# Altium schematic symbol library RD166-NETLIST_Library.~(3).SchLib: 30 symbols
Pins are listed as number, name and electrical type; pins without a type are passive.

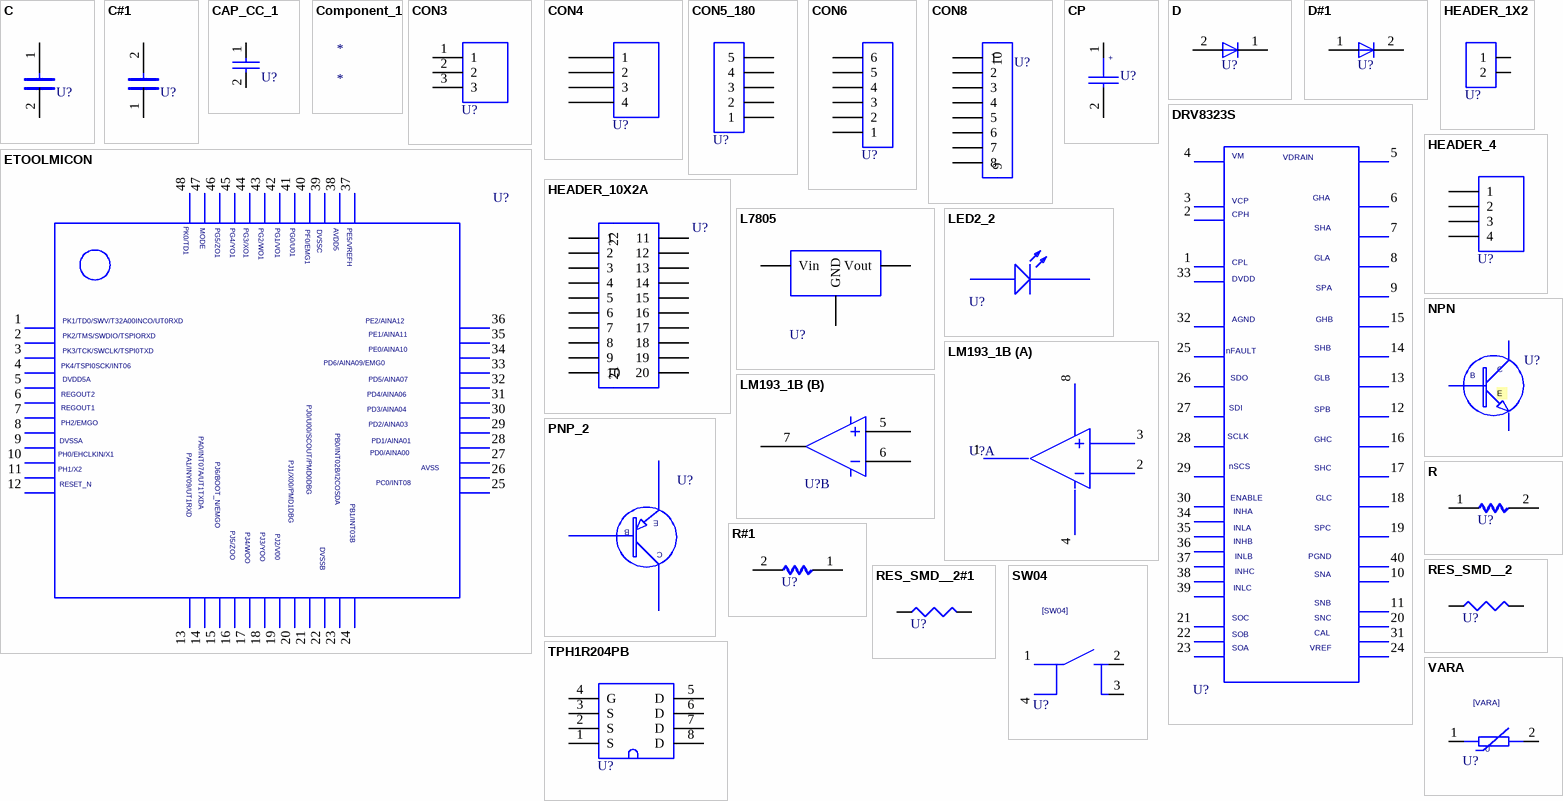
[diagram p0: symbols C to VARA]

## C
designator U?  (value not drawn)
OriginalSymbolOrigin: (2540,7620); Altium-Right: 20; Altium-Bottom: 10
pins: 1 2, 2 1

## C#1
designator U?, comment C  (value not drawn)
OriginalSymbolOrigin: (2540,7620); Altium-Right: 20; Altium-Bottom: 10
pins: 1, 2

## CAP_CC_1
designator U?  (value not drawn)
PARTNAME: CAP-CC_1; OriginalSymbolOrigin: (0,0); SAVECOUNT: 1; UPDATETIME: 14:48:25; UPDATEUSER: d5009410; Altium-Right: 20; Altium-Bottom: 10
pins: 1, 2

## Component_1
designator *

## CON3
designator U?  (value not drawn)
OriginalSymbolOrigin: (0,0); SAVEAREA0: -6361,-10384,8548,546; SAVECOUNT: 2; UPDATETIME: 16:17:55; UPDATEUSER: t5459927; TIME: 14:48:25; Altium-Right: 30; Altium-Bottom: 40
pins: 1, 2, 3

## CON4
designator U?  (value not drawn)
OriginalSymbolOrigin: (0,0); SAVEAREA0: -9538,-12954,9100,710; SAVECOUNT: 2; UPDATETIME: 11:51:19; UPDATEUSER: t5459927; TIME: 14:48:25; Altium-Right: 30; Altium-Bottom: 50
pins: 1, 2, 3, 4

## CON5_180
designator U?  (value not drawn)
OriginalSymbolOrigin: (0,0); SAVEAREA0: -6362,-15544,16003,852; SAVECOUNT: 2; UPDATETIME: 16:18:16; UPDATEUSER: t5459927; TIME: 14:48:25; Altium-Right: 20; Altium-Bottom: 60
pins: 1, 2, 3, 4, 5

## CON6
designator U?  (value not drawn)
OriginalSymbolOrigin: (0,0); SAVEAREA0: -13352,-18135,12740,994; SAVECOUNT: 2; UPDATETIME: 11:51:01; UPDATEUSER: t5459927; TIME: 14:48:25; Altium-Right: 20; Altium-Bottom: 70
pins: 1, 2, 3, 4, 5, 6

## CON8
designator U?  (value not drawn)
OriginalSymbolOrigin: (0,0); SAVEAREA0: -35474,-32561,34839,4331; SAVECOUNT: 3; UPDATETIME: 16:40:52; UPDATEUSER: t5459927; TIME: 14:48:25; Altium-Right: 20; Altium-Bottom: 90
pins: 0 10, 1, 2, 3, 4, 5, 6, 7, 8, 9

## CP
designator U?  (value not drawn)
OriginalSymbolOrigin: (2540,10160); UPDATETIME: 16:13:42; UPDATEUSER: fukuda-y; TIME: 15:02:55; SAVECOUNT: 52; SAVEAREA0: -1450,-153,20294,13055; Altium-Right: 20
pins: 1 2, 2 1

## D
designator U?  (value not drawn)
OriginalSymbolOrigin: (5080,5080); UPDATETIME: 14:20:16; UPDATEUSER: 19870035; TIME: 14:49:55; SAVECOUNT: 3; SAVEAREA0: -225,-91,12804,7836; Altium-Right: 10; Altium-Bottom: 20
pins: 1 C, 2 A

## D#1
designator U?, comment D  (value not drawn)
OriginalSymbolOrigin: (5080,5080); UPDATETIME: 14:20:16; UPDATEUSER: 19870035; TIME: 14:49:55; SAVECOUNT: 3; SAVEAREA0: -225,-91,12804,7836; Altium-Right: 10; Altium-Bottom: 20
pins: 1 A, 2 C

## DRV8323S
designator U?  (value not drawn)
OriginalSymbolOrigin: (-7620,0); SAVEAREA0: -72294,-50031,83425,15115; SAVECOUNT: 5; UPDATETIME: 15:09:32; UPDATEUSER: t5459927; TIME: 14:48:25; Altium-Right: 150; Altium-Bottom: 360
pins: 1, 2, 3, 4, 5, 6, 7, 8, 9, 10, 11, 12, 13, 14, 15, 16, 17, 18, 19, 20, 21, 22, 23, 24, 25, 26, 27, 28, 29, 30, 31, 32, 33, 34, 35, 36, 37, 38, 39, 40

## ETOOLMICON
designator U?  (value not drawn)
OriginalSymbolOrigin: (-10160,7620); SAVEAREA0: -22560,-61894,97211,9095; SAVECOUNT: 11; UPDATETIME: 15:48:18; UPDATEUSER: t5459927; TIME: 14:48:25; Altium-Right: 320; Altium-Bottom: 300
pins: 1, 2, 3, 4, 5, 6, 7, 8, 9, 10, 11, 12, 13, 14, 15, 16, 17, 18, 19, 20, 21, 22, 23, 24, 25, 26, 27, 28, 29, 30, 31, 32, 33, 34, 35, 36, 37, 38, 39, 40, 41, 42, 43, 44, 45, 46, 47, 48

## HEADER_1X2
designator U?  (value not drawn)
PARTNAME: Header 1X2; OriginalSymbolOrigin: (0,0); SAVEAREA0: -1901,-7788,9280,409; SAVECOUNT: 2; UPDATETIME: 11:52:06; UPDATEUSER: t5459927; TIME: 14:48:25; Altium-Right: 20; Altium-Bottom: 30
pins: 1, 2

## HEADER_4
designator U?  (value not drawn)
PARTNAME: Header 4; OriginalSymbolOrigin: (0,0); SAVEAREA0: -8253,-12954,10385,710; SAVECOUNT: 2; UPDATETIME: 17:19:04; UPDATEUSER: t5459927; TIME: 14:48:25; Altium-Right: 30; Altium-Bottom: 50
pins: 1, 2, 3, 4

## HEADER_10X2A
designator U?  (value not drawn)
PARTNAME: Header 10X2A; OriginalSymbolOrigin: (0,0); SAVEAREA0: -38178,-50023,47755,12978; SAVECOUNT: 4; UPDATETIME: 13:19:25; UPDATEUSER: t5459927; TIME: 14:48:25; Altium-Right: 40; Altium-Bottom: 110
pins: 1, 2, 3, 4, 5, 6, 7, 8, 9, 10, 11, 12, 13, 14, 15, 16, 17, 18, 19, 20, 21, 22

## L7805
designator U?  (value not drawn)
OriginalSymbolOrigin: (0,0); SAVEAREA0: -9544,-9544,24191,4569; SAVECOUNT: 2; UPDATETIME: 10:58:54; UPDATEUSER: t5459927; TIME: 14:48:25; Altium-Right: 60; Altium-Bottom: 30
pins: 1 Vin, 2 GND, 3 Vout

## LED2_2
designator U?  (value not drawn)
OriginalSymbolOrigin: (-10160,-3); SAVEAREA0: -21848,-22501,27655,13791; SAVECOUNT: 3; UPDATETIME: 08:39:51; UPDATEUSER: t5459927; TIME: 14:48:25; Altium-Right: 90; Altium-Bottom: 40
pins: 1, 2

## LM193_1B
designator U?  (value not drawn)
OriginalSymbolOrigin: (0,0); SAVECOUNT: 1; UPDATETIME: 14:48:25; UPDATEUSER: d5009410; Altium-Right: 110; Altium-Right1: 40
part A pins: 1, 2, 3, 4, 8
part B pins: 5, 6, 7

## NPN
designator U?  (value not drawn)
OriginalSymbolOrigin: (-2537,2540); SAVEAREA0: -26556,-14535,34190,10878; SAVECOUNT: 4; UPDATETIME: 08:38:55; UPDATEUSER: t5459927; TIME: 14:48:25; Altium-Right: 60; Altium-Bottom: 70
pins: 1, 2, 3

## PNP_2
designator U?  (value not drawn)
OriginalSymbolOrigin: (-10142,10288); SAVEAREA0: -20063,-21887,31766,16111; SAVECOUNT: 5; UPDATETIME: 08:51:01; UPDATEUSER: t5459927; TIME: 14:48:25; Altium-Right: 90; Altium-Bottom: 110
pins: 1, 2, 3

## R
designator U?  (value not drawn)
OriginalSymbolOrigin: (5080,5080); Altium-Right: 20
pins: 1, 2

## R#1
designator U?, comment R  (value not drawn)
OriginalSymbolOrigin: (5080,5080); Altium-Right: 20
pins: 1 2, 2 1

## RES_SMD__2
designator U?  (value not drawn)
PARTNAME: RES(SMD)_2; OriginalSymbolOrigin: (2552,2560); SAVEAREA0: -3866,-5393,16243,5158; SAVECOUNT: 2; UPDATETIME: 10:20:03; UPDATEUSER: t5459927; TIME: 14:48:25; Altium-Right: 30; Altium-Bottom: 20
pins: 1 2, 2 1

## RES_SMD__2#1
designator U?, comment RES_SMD__2  (value not drawn)
PARTNAME: RES(SMD)_2; OriginalSymbolOrigin: (2552,2560); SAVEAREA0: -3866,-5393,16243,5158; SAVECOUNT: 2; UPDATETIME: 10:20:03; UPDATEUSER: t5459927; TIME: 14:48:25; Altium-Right: 30; Altium-Bottom: 20
pins: 1, 2

## SW04
designator U?  (value not drawn)
OriginalSymbolOrigin: (0,10160); SAVECOUNT: 1; UPDATETIME: 18:00:32; UPDATEUSER: 19870035; SAVEAREA0: -7718,-213,22668,18275; Altium-Right: 50; Altium-Bottom: 40
pins: 1, 2, 3 4, 4 3

## TPH1R204PB
designator U?  (value not drawn)
OriginalSymbolOrigin: (0,0); SAVEAREA0: -6015,-14897,18117,2795; SAVECOUNT: 2; UPDATETIME: 14:23:55; UPDATEUSER: t5459927; TIME: 14:48:25; Altium-Right: 50
pins: 1 S, 2 S, 3 S, 4 G, 5 D, 6 D, 7 D, 8 D

## VARA
designator U?  (value not drawn)
OriginalSymbolOrigin: (2540,5080); UPDATETIME: 09:56:50; UPDATEUSER: tomizawa-y; SAVECOUNT: 12; SAVEAREA0: -9950,-8554,25168,13619; Altium-Right: 40; Altium-Bottom: 20
pins: 1, 2

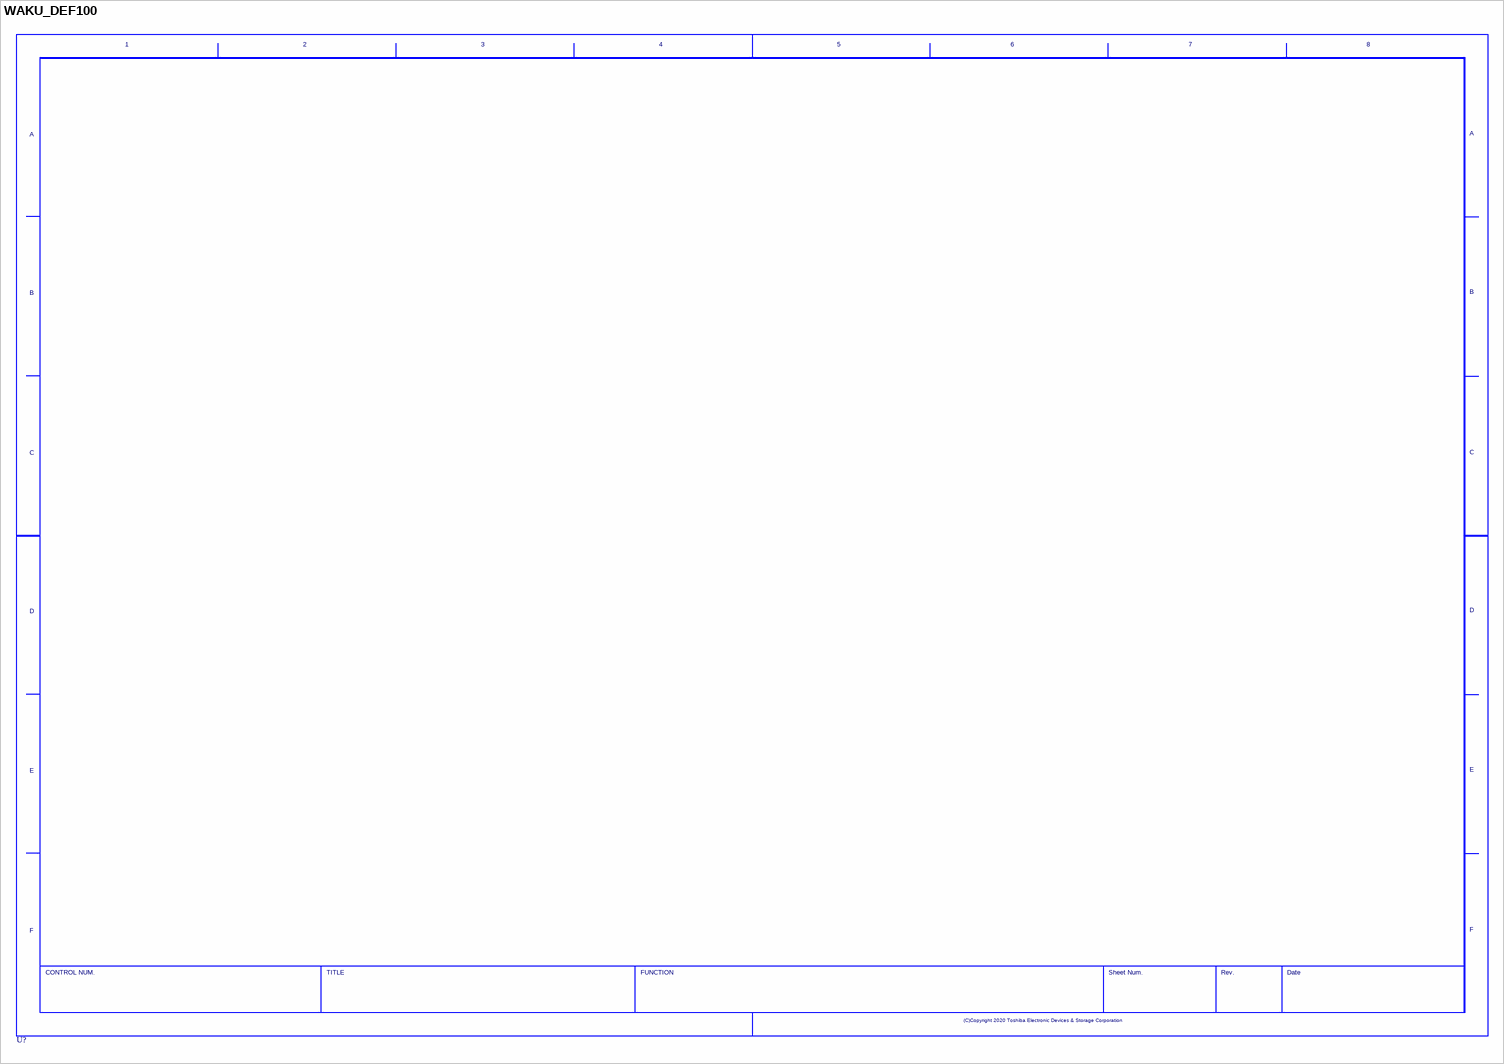
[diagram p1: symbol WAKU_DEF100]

## WAKU_DEF100
designator U?  (value not drawn)
OriginalSymbolOrigin: (10160,284480); SAVECOUNT: 5; UPDATETIME: 15:33:12; UPDATEUSER: t5459927; TIME: 14:30:25; SAVEAREA0: 131320,-65800,503440,89880; PLOTTIME: HH:MM; Altium-Right: 1570; Altium-Bottom: 1070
